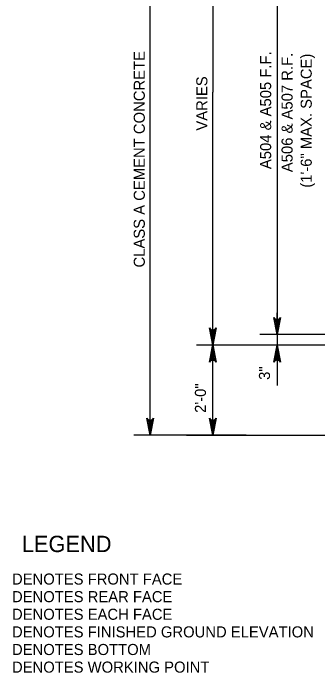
# Model space of a CAD drawing. Extents: x 638255 to 640306, y 296059 to 298435.
# Drawn here: x 638968.7 to 639051.2, y 298139.9 to 298318.6 of the extents above; entities that cross this region are included whole.
import ezdxf

# ---------------------------------------------------------------- set-up
doc = ezdxf.new("R2010")
doc.units = 0
doc.layers.add('Level 3', color=7, linetype='Continuous')
doc.layers.add('Level 4', color=7, linetype='Continuous')

msp = doc.modelspace()

# ---------------------------------------------------------------- linework, layer by layer
at = {"layer": 'Level 3'}
for p, q in [((639005.81, 298204.3), (639005.81, 298365.71)), ((639022.78, 298365.71), (639022.78, 298297.2)), ((639040.23, 298354.82), (639040.23, 298231.52)), ((639022.78, 298228.68), (639022.78, 298297.2)), ((639057.87, 298231.52), (639035.54, 298231.52)), ((639040.23, 298231.52), (639040.23, 298217.76)), ((639073.88, 298228.68), (639018.36, 298228.68)), ((639022.78, 298204.3), (639022.78, 298228.68)), ((639048.36, 298228.68), (639035.81, 298228.68)), ((639040.23, 298225.74), (639040.23, 298222.79)), ((639031.84, 298204.3), (639001.39, 298204.3))]:
    msp.add_line(p, q, dxfattribs=at)
for points in [[(639040.23, 298231.52), (639039.36, 298236.17), (639039.61, 298235.82), (639039.92, 298235.63), (639040.23, 298235.58), (639040.55, 298235.63), (639040.86, 298235.82), (639041.11, 298236.17), (639040.23, 298231.52), (639040.86, 298235.82), (639040.55, 298235.63), (639040.23, 298231.52), (639040.23, 298235.58), (639039.92, 298235.63), (639040.23, 298231.52), (639039.61, 298235.82)], [(639022.78, 298228.68), (639021.91, 298233.33), (639022.16, 298232.98), (639022.47, 298232.79), (639022.78, 298232.74), (639023.09, 298232.79), (639023.41, 298232.98), (639023.65, 298233.33), (639022.78, 298228.68), (639023.41, 298232.98), (639023.09, 298232.79), (639022.78, 298228.68), (639022.78, 298232.74), (639022.47, 298232.79), (639022.78, 298228.68), (639022.16, 298232.98)], [(639022.78, 298228.68), (639023.65, 298224.03), (639023.41, 298224.39), (639023.09, 298224.57), (639022.78, 298224.63), (639022.47, 298224.57), (639022.16, 298224.39), (639021.91, 298224.03), (639022.78, 298228.68), (639022.16, 298224.39), (639022.47, 298224.57), (639022.78, 298228.68), (639022.78, 298224.63), (639023.09, 298224.57), (639022.78, 298228.68), (639023.41, 298224.39)], [(639040.23, 298228.68), (639041.11, 298224.03), (639040.86, 298224.39), (639040.55, 298224.57), (639040.23, 298224.63), (639039.92, 298224.57), (639039.61, 298224.39), (639039.36, 298224.03), (639040.23, 298228.68), (639039.61, 298224.39), (639039.92, 298224.57), (639040.23, 298228.68), (639040.23, 298224.63), (639040.55, 298224.57), (639040.23, 298228.68), (639040.86, 298224.39)], [(639005.81, 298204.3), (639004.94, 298208.95), (639005.19, 298208.59), (639005.5, 298208.4), (639005.81, 298208.35), (639006.12, 298208.4), (639006.43, 298208.59), (639006.68, 298208.95), (639005.81, 298204.3), (639006.43, 298208.59), (639006.12, 298208.4), (639005.81, 298204.3), (639005.81, 298208.35), (639005.5, 298208.4), (639005.81, 298204.3), (639005.19, 298208.59)], [(639022.78, 298204.3), (639021.91, 298208.95), (639022.16, 298208.59), (639022.47, 298208.4), (639022.78, 298208.35), (639023.09, 298208.4), (639023.41, 298208.59), (639023.65, 298208.95), (639022.78, 298204.3), (639023.41, 298208.59), (639023.09, 298208.4), (639022.78, 298204.3), (639022.78, 298208.35), (639022.47, 298208.4), (639022.78, 298204.3), (639022.16, 298208.59)]]:
    msp.add_lwpolyline(points, dxfattribs=at)
for points in [[(639039.74, 298234.47), (639040.73, 298234.47), (639040.23, 298231.52)], [(639023.27, 298231.63), (639022.29, 298231.63), (639022.78, 298228.68)], [(639023.27, 298226), (639022.29, 298226), (639022.78, 298228.95)], [(639039.74, 298225.74), (639040.73, 298225.74), (639040.23, 298228.68)], [(639005.32, 298207.24), (639006.3, 298207.24), (639005.81, 298204.3)], [(639023.27, 298207.24), (639022.29, 298207.24), (639022.78, 298204.3)]]:
    msp.add_lwpolyline(points, close=True, dxfattribs=at)
at = {"layer": 'Level 4'}
for p, q in [((639040.23, 298234.47), (639040.23, 298237.42)), ((639015.65, 298204.3), (639074.5, 298204.3))]:
    msp.add_line(p, q, dxfattribs=at)

# ---------------------------------------------------------------- texts
at = {"layer": 'Level 3'}
for s, height, p in [('CLASS A CEMENT CONCRETE', 3.0001, (639004.36, 298249.71)), ('A504 & A505 F.F.', 3.0001, (639038.6, 298276.35)), ('A506 & A507 R.F.', 3.0001, (639044.41, 298275.52)), ('(1\'-6" MAX. SPACE)', 3.0001, (639049.59, 298271.32)), ('VARIES', 3, (639021.31, 298286.77)), ('3"', 3, (639038.28, 298219.28)), ('2\'-0"', 3, (639020.93, 298210.34))]:
    msp.add_text(s, height=height, rotation=90, dxfattribs=at).set_placement(p)
for s, height, p in [('LEGEND', 4.421, (638971.03, 298172.64)), ('DENOTES FRONT FACE', 3.0001, (638968.37, 298163.84)), ('DENOTES REAR FACE', 3.0001, (638968.37, 298159.07)), ('DENOTES EACH FACE', 3.0001, (638968.37, 298154.3)), ('DENOTES FINISHED GROUND ELEVATION', 3.0001, (638968.37, 298149.53)), ('DENOTES BOTTOM', 3.0001, (638968.37, 298144.76)), ('DENOTES WORKING POINT', 3.0001, (638968.37, 298139.99))]:
    msp.add_text(s, height=height, dxfattribs=at).set_placement(p)

doc.saveas('drawing.dxf')
